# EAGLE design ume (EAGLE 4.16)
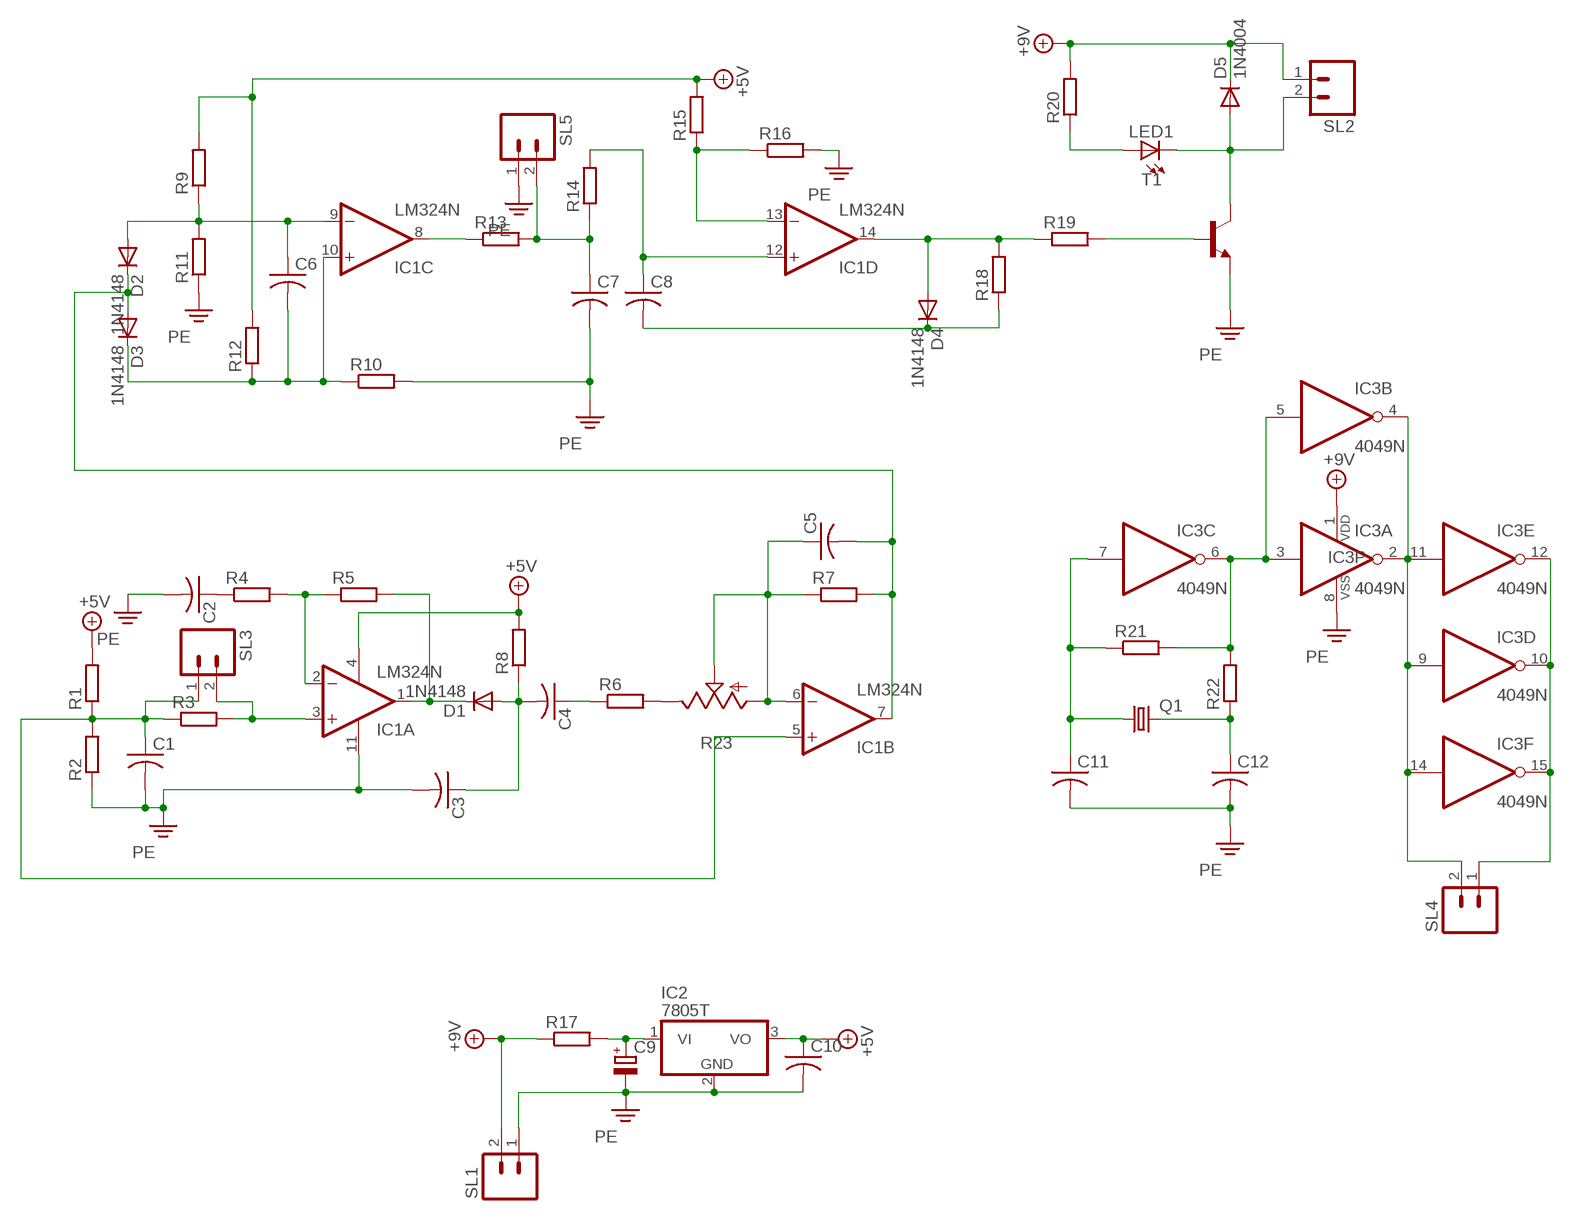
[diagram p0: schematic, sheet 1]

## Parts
C1  C-US050-050X075  [C050-050X075]
C2  C-US050-050X075  [C050-050X075]
C3  C-US050-050X075  [C050-050X075]
C4  C-US050-050X075  [C050-050X075]
C5  C-US050-050X075  [C050-050X075]
C6  C-US050-050X075  [C050-050X075]
C7  C-US050-050X075  [C050-050X075]
C8  C-US050-050X075  [C050-050X075]
C9  CPOL-EUE5-8.5  [E5-8,5]
C10  C-US050-050X075  [C050-050X075]
C11  C-US050-050X075  [C050-050X075]
C12  C-US050-050X075  [C050-050X075]
D1  1N4148  [DO35-10]
D2  1N4148  [DO35-10]
D3  1N4148  [DO35-10]
D4  1N4148  [DO35-10]
D5  1N4004  [DO41-10]
IC1  LM324N  [DIL14]
IC2  7805T  [TO220H]
IC3  4049N  [DIL16]
LED1  LED5MM  [LED5MM]
Q1  CRYSTALHC49S  [HC49/S]
R1  R-EU_0309/10  [0309/10]
R2  R-EU_0309/10  [0309/10]
R3  R-EU_0309/10  [0309/10]
R4  R-EU_0309/10  [0309/10]
R5  R-EU_0309/10  [0309/10]
R6  R-EU_0309/10  [0309/10]
R7  R-EU_0309/10  [0309/10]
R8  R-EU_0309/10  [0309/10]
R9  R-EU_0309/10  [0309/10]
R10  R-EU_0309/10  [0309/10]
R11  R-EU_0309/10  [0309/10]
R12  R-EU_0309/10  [0309/10]
R13  R-EU_0309/10  [0309/10]
R14  R-EU_0309/10  [0309/10]
R15  R-EU_0309/10  [0309/10]
R16  R-EU_0309/10  [0309/10]
R17  R-EU_0309/10  [0309/10]
R18  R-EU_0309/10  [0309/10]
R19  R-EU_0309/10  [0309/10]
R20  R-EU_0309/10  [0309/10]
R21  R-EU_0309/10  [0309/10]
R22  R-EU_0309/10  [0309/10]
R23  TRIM_US-LI15  [LI15]
SL1  M02  [02P]
SL2  M02  [02P]
SL3  M02  [02P]
SL4  M02  [02P]
SL5  M02  [02P]
T1  -NPN-TO92  [TO92]

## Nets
+5V: C10.1 IC1.4(P:V+) IC2.3(VO) R1.2 R8.2 R9.2 R12.2 R15.2
+9V: D5.C IC3.1(P:VDD) R17.1 R20.2 SL1.2 SL2.1
N$1: C6.1 D2.A IC1.9(C:-IN) R9.1 R11.2
N$2: C5.2 D2.C D3.A IC1.7(B:OUT) R7.2
N$3: R19.2 T1.2(B)
N$4: C6.2 D3.C IC1.10(C:+IN) R10.1 R12.1
N$5: IC1.2(A:-IN) R4.2 R5.1
N$6: IC1.3(A:+IN) R3.2 SL3.2
N$7: C1.1 IC1.5(B:+IN) R1.1 R2.2 R3.1 SL3.1
N$8: D1.C IC1.1(A:OUT) R5.2
N$9: C3.1 C4.2 D1.A R8.1
N$10: IC1.8(C:OUT) R13.1
N$11: C7.1 R13.2 R14.1 SL5.2
N$12: IC1.13(D:-IN) R15.1 R16.1
N$13: C8.1 IC1.12(D:+IN) R14.2
N$14: C2.1 R4.1
N$15: C8.2 D4.C R18.1
N$16: D4.A IC1.14(D:OUT) R18.2 R19.1
N$17: C4.1 R6.1
N$18: C5.1 IC1.6(B:-IN) R7.1 R23.A R23.S
N$19: D5.A LED1.K(C) SL2.2 T1.3(C)
N$20: LED1.A R20.1
N$21: R6.2 R23.E
N$22: C12.1 Q1.2 R22.1
N$23: IC3.3(A:I) IC3.5(B:I) IC3.6(C:O) R21.2 R22.2
N$24: C9.+ IC2.1(VI) R17.2
N$27: C11.1 IC3.7(C:I) Q1.1 R21.1
N$28: IC3.2(A:O) IC3.4(B:O) IC3.9(D:I) IC3.11(E:I) IC3.14(F:I) SL4.2
N$30: IC3.10(D:O) IC3.12(E:O) IC3.15(F:O) SL4.1
PE: C1.2 C2.2 C3.2 C7.2 C9.- C10.2 C11.2 C12.2 IC1.11(P:V-) IC2.2(GND) IC3.8(P:VSS) R2.1 R10.2 R11.1 R16.2 SL1.1 SL5.1 T1.1(E)

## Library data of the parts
C1-C8 C10-C12 = rcl:C-US: CAPACITOR, American symbol
C9 = rcl:CPOL-EU: POLARIZED CAPACITOR, European symbol
D1-D4 = diode:1N4148: DIODE
D5 = diode:1N4004: DIODE
IC1 = linear:LM324: OP AMP
IC2 = linear:78*: Positive VOLTAGE REGULATOR Source: http://cache.national.com/ds/LM/LM78L05.pdf http://www.fairchildsemi.com/ds/LM/LM7805.pdf
IC3 = 40xx:4049: Hex inverting BUFFER
LED1 = led:LED: LED
Q1 = crystal:CRYSTAL: CRYSTAL
R1-R22 = rcl:R-EU_: RESISTOR, European symbol
R23 = pot:TRIM_US-: POTENTIOMETER
SL1-SL5 = con-amp-quick:M02: AMP QUICK CONNECTOR
T1 = transistor:*-NPN-: NPN Transistror

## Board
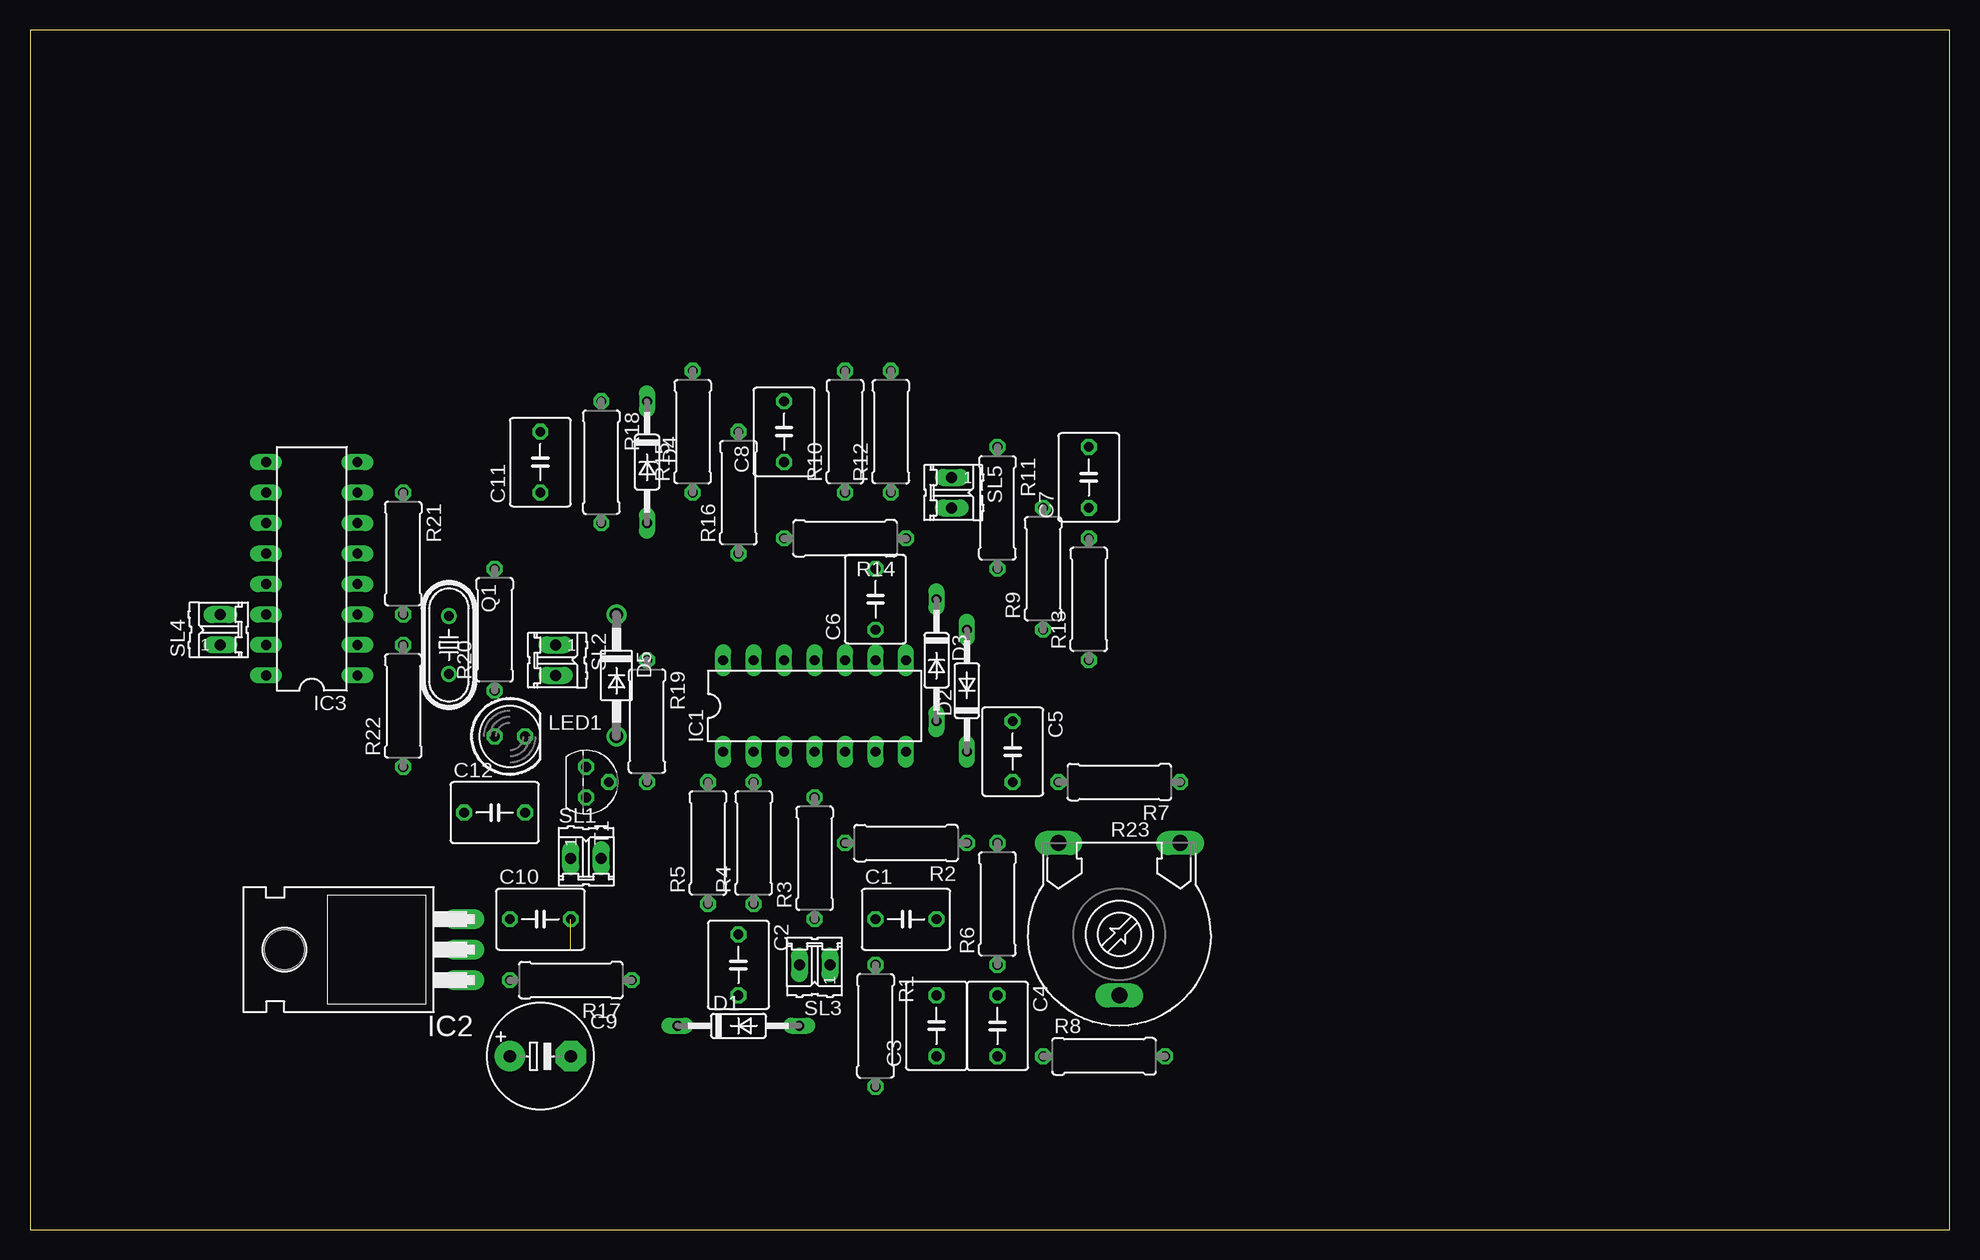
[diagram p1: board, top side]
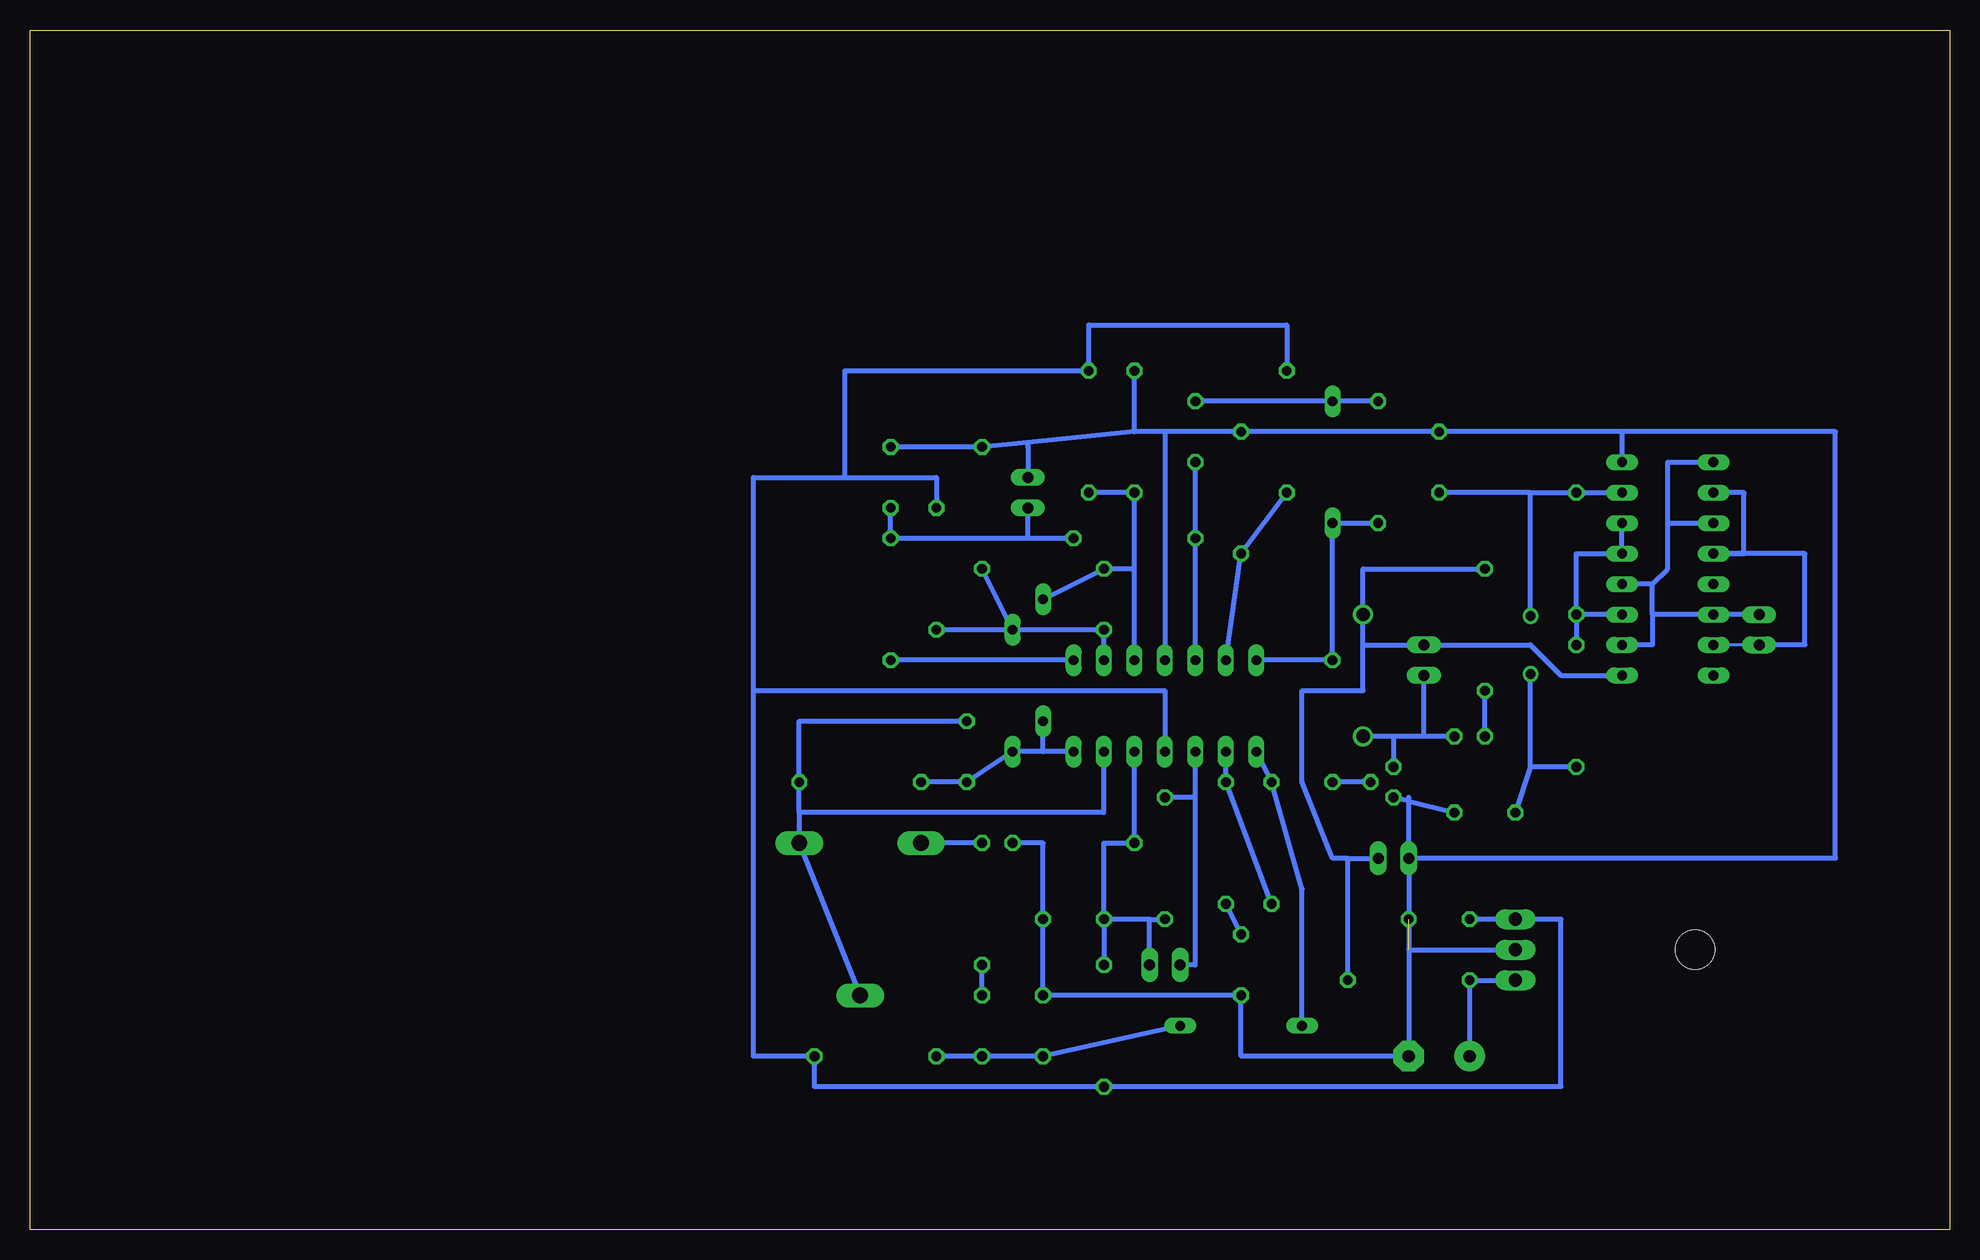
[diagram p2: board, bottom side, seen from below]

Size 160 x 100 mm. Coordinates in mm from the lower left corner, seen from the top.
Outline: 0,0 160,0 160,100 0,100 0,0
Copper layers (1*16): Fls 0.035mm / dielectric 1.5mm / Alsó   0.035mm
Design rules "default": minimum track width 10mil, minimum drill 24mil, track to track 8mil, track to pad 8mil, pad to pad 8mil, via to via 8mil, smd to smd 8mil, copper to edge 40mil, drill to drill 8mil, minimum pad ring 10mil, minimum via ring 8mil, stop-mask expansion 4mil, vias tented up to drill 0mil, thermal gap 10mil

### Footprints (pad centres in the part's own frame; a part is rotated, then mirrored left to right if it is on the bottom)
C050-050X075 = drill 0.813 octagon: 1 -2.54,0; 2 2.54,0
E5-8,5 = drill 1.016 pad 2.54 round: + -2.54,0 | drill 1.016 pad 2.54 octagon: - 2.54,0
DO35-10 = drill 0.813 long: A 5.08,0; C -5.08,0
DO41-10 = drill 1.118 round: A 5.08,0; C -5.08,0
DIL14 = drill 0.813 long: 1 -7.62,-3.81; 2 -5.08,-3.81; 3 -2.54,-3.81; 4 0,-3.81; 5 2.54,-3.81; 6 5.08,-3.81; 7 7.62,-3.81; 8 7.62,3.81; 9 5.08,3.81; 10 2.54,3.81; 11 0,3.81; 12 -2.54,3.81; 13 -5.08,3.81; 14 -7.62,3.81
TO220H = drill 1.118 long: 1 -2.54,-10.16; 2 0,-10.16; 3 2.54,-10.16 | hole 3.302: 0,4.826
DIL16 = drill 0.813 long: 1 -8.89,-3.81; 2 -6.35,-3.81; 3 -3.81,-3.81; 4 -1.27,-3.81; 5 1.27,-3.81; 6 3.81,-3.81; 7 6.35,-3.81; 8 8.89,-3.81; 9 8.89,3.81; 10 6.35,3.81; 11 3.81,3.81; 12 1.27,3.81; 13 -1.27,3.81; 14 -3.81,3.81; 15 -6.35,3.81; 16 -8.89,3.81
LED5MM = drill 0.813 octagon: A -1.27,0; K 1.27,0
HC49/S = drill 0.813 round: 1 -2.413,0; 2 2.413,0
0309/10 = drill 0.813 octagon: 1 -5.08,0; 2 5.08,0
LI15 = drill 1.321 long: A -5.08,-7.62; E 5.08,-7.62; S 0,5.08
02P = drill 0.914 long: 1 -1.27,0; 2 1.27,0
TO92 = drill 0.813 octagon: 1 1.27,0; 2 0,1.905; 3 -1.27,0

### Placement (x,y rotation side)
C1  73.02,25.87 0 top
C2  59.05,22.06 270 top
C3  75.56,16.98 90 top
C4  80.64,16.98 270 top
C5  81.91,39.84 270 top
C6  70.48,52.54 90 top
C7  88.26,62.7 90 top
C8  62.86,66.51 90 top
C9  42.54,14.44 0 top
C10  42.54,25.87 0 top
C11  42.54,63.97 90 top
C12  38.73,34.76 0 top
D1  59.05,16.98 0 top
D2  78.1,44.92 90 top
D3  75.56,47.46 270 top
D4  51.43,63.97 270 top
D5  48.89,46.19 270 top
IC1  65.4,43.65 0 top
IC2  26.03,23.33 90 top
IC3  23.49,55.08 90 top
LED1  40,41.11 0 top
Q1  34.92,48.73 270 top
R1  70.48,16.98 270 top
R2  73.02,32.22 180 top
R3  65.4,30.95 90 top
R4  60.32,32.22 90 top
R5  56.51,32.22 90 top
R6  80.64,27.14 90 top
R7  90.8,37.3 180 top
R8  89.53,14.44 0 top
R9  84.45,55.08 90 top
R10  67.94,66.51 90 top
R11  80.64,60.16 270 top
R12  71.75,66.51 90 top
R13  88.26,52.54 90 top
R14  67.94,57.62 180 top
R15  55.24,66.51 90 top
R16  59.05,61.43 90 top
R17  45.08,20.79 180 top
R18  47.62,63.97 270 top
R19  51.43,42.38 270 top
R20  38.73,50 90 top
R21  31.11,56.35 270 top
R22  31.11,43.65 90 top
R23  90.8,24.6 180 top
SL1  46.35,30.95 0 top
SL2  43.81,47.46 270 top
SL3  65.4,22.06 180 top
SL4  15.87,50 90 top
SL5  76.83,61.43 270 top
T1  46.35,37.3 270 top

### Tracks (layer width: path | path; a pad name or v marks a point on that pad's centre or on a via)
+5V
  Alsó   0.406: 92.07,62.7 92.07,71.59 R12.2 71.75,75.4 55.24,75.4 R15.2 | 92.07,62.7 84.45,62.7 R9.2 | 99.69,44.92 99.69,14.44 R8.2 94.61,11.9 R1.2 32.38,11.9 32.38,25.87 IC2.3 C10.1 | 99.69,44.92 99.69,62.7 92.07,62.7 | IC1.4 65.4,44.92 99.69,44.92
+9V
  Alsó   0.406: R20.2 48.89,55.08 D5.C 48.89,48.73 | 48.89,48.73 SL2.1 34.92,48.73 32.38,46.19 IC3.1 | 50.16,30.95 SL1.2 | 50.16,30.95 51.43,30.95 53.97,37.3 53.97,44.92 48.89,44.92 48.89,48.73 | R17.1 50.16,30.95
N$1
  Alsó   0.406: IC1.9 C6.1 D2.A | D2.A R9.1 | D2.A R11.2
N$2
  Alsó   0.406: R7.2 C5.2 D2.C 75.56,39.84 | IC1.7 75.56,39.84 | 75.56,39.84 D3.A
N$3
  Alsó   0.406: T1.2 R19.2
N$4
  Alsó   0.406: R12.1 R10.1 67.94,55.08 | IC1.10 67.94,55.08 | 67.94,55.08 C6.2 D3.C
N$5
  Alsó   0.406: IC1.2 R4.2 R5.1
N$6
  Alsó   0.406: 62.86,36.03 IC1.3 | 62.86,36.03 R3.2 | SL3.2 62.86,22.06 62.86,36.03
N$7
  Alsó   0.406: 66.67,25.87 R3.1 | 66.67,25.87 C1.1 | C1.1 70.48,32.22 R2.2 IC1.5 | SL3.1 66.67,25.87 | C1.1 R1.1
N$8
  Alsó   0.406: IC1.1 R5.2 53.97,28.41 D1.C
N$9
  Alsó   0.406: D1.A C3.1 C4.2 R8.1
N$10
  Alsó   0.406: IC1.8 R13.1
N$11
  Alsó   0.406: C7.1 R13.2 76.83,57.62 | R14.1 76.83,57.62 | 76.83,57.62 SL5.2
N$12
  Alsó   0.406: IC1.13 R16.1 R15.1
N$13
  Alsó   0.406: IC1.12 R14.2 C8.1
N$14
  Alsó   0.406: C2.1 R4.1
N$15
  Alsó   0.406: C8.2 D4.C R18.1
N$16
  Alsó   0.406: IC1.14 R19.1 D4.A R18.2
N$17
  Alsó   0.406: C4.1 R6.1
N$18
  Alsó   0.406: C5.1 95.88,42.38 R7.1 95.88,34.76 | R23.S R23.A 95.88,34.76 | IC1.6 70.48,34.76 95.88,34.76
N$19
  Alsó   0.406: LED1.K 43.81,41.11 | 43.81,41.11 46.35,41.11 | 46.35,41.11 D5.A | 46.35,41.11 T1.3 | 43.81,41.11 SL2.2
N$20
  Alsó   0.406: LED1.A R20.1
N$21
  Alsó   0.406: R6.2 R23.E
N$22
  Alsó   0.406: R22.1 34.92,38.57 | 34.92,38.57 C12.1 | 34.92,38.57 Q1.2
N$23
  Alsó   0.406: R21.2 R22.2 | IC3.3 R21.2 | IC3.6 IC3.5 31.11,56.35 R21.2
N$24
  Alsó   0.406: IC2.1 R17.2 C9.+
N$27
  Alsó   0.406: 34.92,61.43 R21.1 IC3.7 | 34.92,61.43 C11.1 | Q1.1 34.92,61.43
N$28
  Alsó   0.406: 24.76,53.81 IC3.4 | 24.76,51.27 24.76,48.73 IC3.2 | 24.76,51.27 24.76,53.81 | IC3.9 23.49,63.97 23.49,58.89 | 23.49,58.89 23.49,55.08 24.76,53.81 | 23.49,58.89 IC3.11 | SL4.2 IC3.14 24.76,51.27
N$30
  Alsó   0.254: SL4.1 IC3.15
  Alsó   0.406: IC3.10 17.14,61.43 17.14,56.35 IC3.12 12.06,56.35 12.06,48.73 SL4.1
PE  (1 unrouted)
  Alsó   0.406: 65.4,66.51 R16.2 C11.2 27.3,66.51 | 65.4,66.51 67.94,66.51 | 67.94,66.51 R10.2 | C7.2 R11.1 76.87,65.62 | 67.94,66.51 76.87,65.62 | 45.08,23.33 C9.- 59.05,14.44 C2.2 C3.2 C1.2 75.56,32.22 R2.1 | 45.08,23.33 IC2.2 | SL1.1 45.08,23.33 | 45.16,35.73 C12.2 | 45.16,35.73 T1.1 | 45.16,35.73 45.08,36.03 SL1.1 | 76.87,65.62 76.83,65.24 SL5.1 | 27.3,66.51 9.52,66.51 9.52,30.95 SL1.1 | 27.3,66.51 IC3.8 | 65.4,66.51 IC1.11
